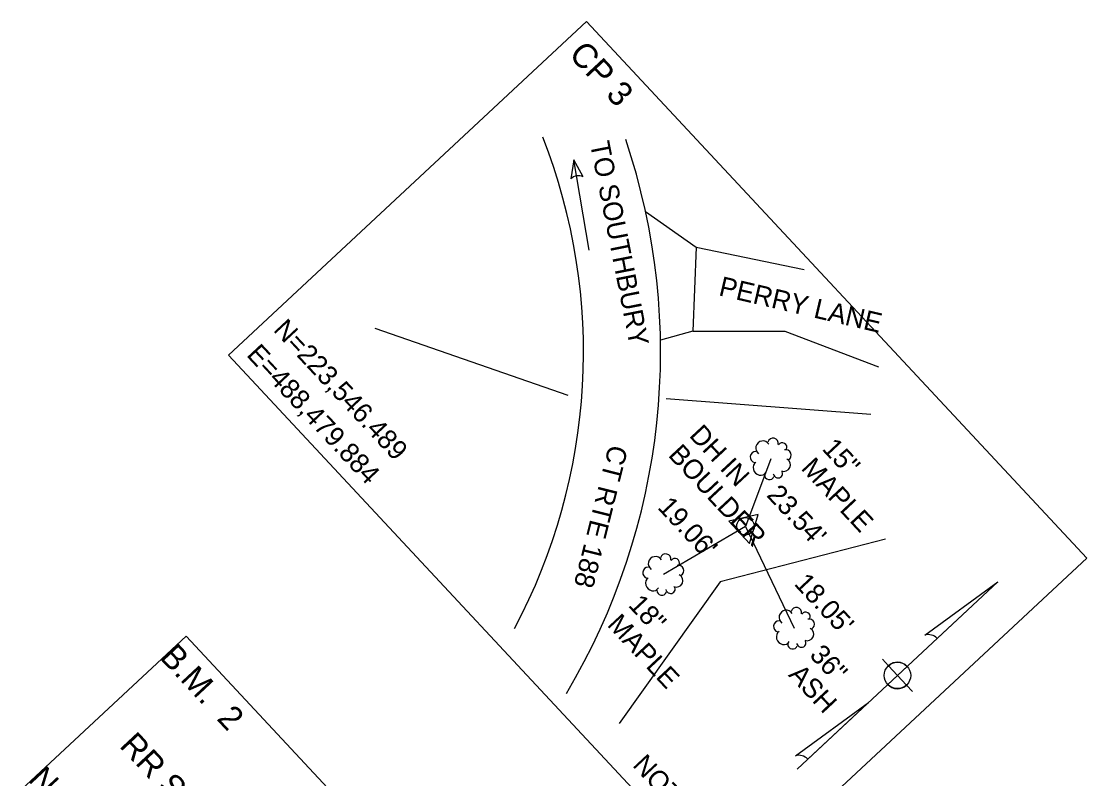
# Model space of a CAD drawing. Extents: x 487096 to 489566, y 221939 to 224454.
# Drawn here: x 488529.7 to 488704, y 223512.7 to 223636.5 of the extents above; entities that cross this region are included whole.
import ezdxf

# ---------------------------------------------------------------- set-up
doc = ezdxf.new("R2010")
doc.units = 0
doc.layers.add('SV_CTRL_BM_INFO_BOX', color=7, linetype='Continuous')
doc.layers.add('SV_CTRL_TIE_BOX', color=7, linetype='Continuous')

msp = doc.modelspace()

# ---------------------------------------------------------------- linework, layer by layer
at = {"layer": 'SV_CTRL_BM_INFO_BOX'}
msp.add_lwpolyline([(488556.68, 223535.96), (488642.46, 223443.98), (488615.51, 223418.85), (488529.73, 223510.83)], close=True, dxfattribs=at)
at = {"layer": 'SV_CTRL_TIE_BOX'}
for p, q in [((488620.13, 223613.86), (488619.64, 223610.73)), ((488622.64, 223599.07), (488620.13, 223613.86)), ((488621.62, 223611.07), (488620.13, 223613.86)), ((488640.14, 223599.58), (488657.8, 223595.93)), ((488619.21, 223575.33), (488587.59, 223586.3)), ((488668.67, 223572.19), (488635.24, 223574.77)), ((488652.36, 223564.95), (488652.36, 223564.95)), ((488650.28, 223555.88), (488645.44, 223554.76)), ((488645.44, 223554.76), (488648.83, 223551.13)), ((488648.83, 223551.13), (488650.28, 223555.88)), ((488648.18, 223553.92), (488634.78, 223546.04)), ((488648.18, 223553.92), (488648.18, 223553.92)), ((488634.78, 223546.04), (488634.78, 223546.04)), ((488656.63, 223514.24), (488689.47, 223544.86)), ((488656.17, 223537.26), (488656.17, 223537.26)), ((488679.53, 223535.6), (488679.53, 223535.6)), ((488679.53, 223535.6), (488679.53, 223535.6)), ((488670.59, 223532.19), (488671.58, 223531.13)), ((488671.58, 223531.13), (488673.05, 223529.55)), ((488673.05, 223529.55), (488674.63, 223531.03)), ((488671.47, 223528.08), (488673.05, 223529.55)), ((488673.05, 223529.55), (488673.05, 223529.55)), ((488673.05, 223529.55), (488674.52, 223527.97)), ((488674.52, 223527.97), (488675.5, 223526.92)), ((488656.37, 223516.41), (488668.3, 223525.12)), ((488658.36, 223515.85), (488668.3, 223525.12)), ((488668.3, 223525.12), (488658.36, 223515.86))]:
    msp.add_line(p, q, dxfattribs=at)
msp.add_lwpolyline([(488563.65, 223581.94), (488645.49, 223494.18), (488704, 223548.74), (488622.16, 223636.5)], close=True, dxfattribs=at)
for points in [[(488631.85, 223605.39), (488640.14, 223599.58), (488639.55, 223585.83), (488634.29, 223584.34)], [(488639.55, 223585.83), (488654.63, 223585.84), (488669.94, 223579.99)], [(488652.36, 223564.95), (488648.18, 223553.92), (488656.17, 223537.26)], [(488671.1, 223551.82), (488644.07, 223544.84), (488627.53, 223521.67)], [(488677.54, 223536.15), (488689.47, 223544.86), (488679.53, 223535.6), (488679.53, 223535.6)], [(488677.54, 223536.15), (488689.47, 223544.86), (488679.53, 223535.6), (488679.53, 223535.6)], [(488677.54, 223536.15), (488689.47, 223544.86), (488679.53, 223535.6), (488679.53, 223535.6)]]:
    msp.add_lwpolyline(points, dxfattribs=at)
for centre, radius in [((488648.18, 223553.92), 1.43), ((488673.05, 223529.55), 2.16)]:
    msp.add_circle(centre, radius, dxfattribs=at)
for centre, radius, start, end in [((488525.52, 223582.41), 96.17, 331.9856, 21.4355), ((488525.52, 223582.41), 108.78, 329.1397, 18.641), ((488620.85, 223609.62), 1.64, 62.0409, 137.2426), ((488651.04, 223566.72), 1.17, 32.3292, 232.9889), ((488652.7, 223567.47), 0.874, 348.9933, 164.459), ((488654.22, 223566.84), 0.75, 336.2911, 145.3579), ((488649.88, 223565.26), 0.922, 90.0157, 257.5501), ((488654.82, 223565.59), 0.85, 298.5308, 105.7093), ((488654.48, 223563.97), 1.06, 247.1859, 64.1082), ((488635.12, 223548.55), 0.874, 348.9933, 164.459), ((488633.46, 223547.81), 1.17, 32.3292, 232.9889), ((488636.64, 223547.93), 0.75, 336.2911, 145.3579), ((488632.3, 223546.35), 0.922, 90.0157, 257.5501), ((488636.9, 223545.05), 1.06, 247.1859, 64.1082), ((488637.24, 223546.68), 0.85, 298.5308, 105.7093), ((488656.5, 223539.78), 0.874, 348.9933, 164.459), ((488654.85, 223539.04), 1.17, 32.3292, 232.9889), ((488658.03, 223539.15), 0.75, 336.2911, 145.3579), ((488653.69, 223537.57), 0.922, 90.0157, 257.5501), ((488658.29, 223536.28), 1.06, 247.1859, 64.1082), ((488658.62, 223537.91), 0.85, 298.5308, 105.7093), ((488678.08, 223534.24), 1.99, 43, 105.6885), ((488678.08, 223534.24), 1.99, 43, 105.6885), ((488673.05, 223529.55), 2.16, 43, 132.985), ((488673.05, 223529.55), 2.18, 223, 313.0149), ((488656.91, 223514.5), 1.99, 43, 105.6885)]:
    msp.add_arc(centre, radius, start, end, dxfattribs=at)
for centre, major_axis, ratio, start_param, end_param in [((488650.57, 223563.45), (-0.699, 0.983), 0.902156, 0, 3.5401), ((488652.09, 223562.35), (-0.529, -0.603), 0.999752, 5.391582, 8.241319), ((488653.47, 223562.63), (0.551, -0.61), 0.901056, 4.216583, 7.444153), ((488632.98, 223544.54), (-0.699, 0.983), 0.902156, 0, 3.5401), ((488634.51, 223543.44), (-0.529, -0.603), 0.999752, 5.391582, 8.241319), ((488635.89, 223543.72), (0.551, -0.61), 0.901056, 4.216583, 7.444153), ((488654.37, 223535.76), (-0.699, 0.983), 0.902156, 0, 3.5401), ((488655.9, 223534.66), (-0.529, -0.603), 0.999752, 5.391582, 8.241319), ((488657.28, 223534.94), (0.551, -0.61), 0.901056, 4.216583, 7.444153)]:
    msp.add_ellipse(centre, major_axis=major_axis, ratio=ratio, start_param=start_param, end_param=end_param, dxfattribs=at)

# ---------------------------------------------------------------- texts
at = {"layer": 'SV_CTRL_BM_INFO_BOX'}
for s, p in [(' B.M.  2   ', (488551.2, 223533.51)), (' RR SPIKE IN 24" MAPLE                    ', (488544.64, 223519.01)), (' NGVD 1929', (488529.72, 223513.48))]:
    msp.add_text(s, height=3.937, rotation=313, dxfattribs=at).set_placement(p)
at = {"layer": 'SV_CTRL_TIE_BOX'}
for s, height, rotation, p in [('CP 3                           ', 4, 312.965, (488619.13, 223630.95)), ('TO SOUTHBURY', 3.2, 281.1204, (488622.73, 223616.56)), ('PERRY LANE', 3.2, 346.851, (488643.67, 223591.72)), ('N=223,546.489  ', 3.2, 313, (488570.83, 223585.96)), ('E=488,479.884  ', 3.2, 313, (488566.44, 223581.87)), ('DH IN', 3.2, 313, (488638.84, 223568.69)), ('CT RTE 188', 3.2, 255.9052, (488625.89, 223567.41)), ('BOULDER', 3.2, 313, (488635.4, 223565.48)), ('15"', 3.2, 313, (488660.57, 223566.52)), ('MAPLE', 3.2, 313, (488657.13, 223563.31)), ("23.54'", 3.2, 313, (488651.51, 223558.92)), ("19.06'", 3.2, 313, (488633.66, 223556.94)), ("18.05'", 3.2, 313, (488656, 223544.44)), ('18"', 3.2, 313, (488628.87, 223540.94)), ('MAPLE', 3.2, 313, (488625.43, 223537.74)), ('36"', 3.2, 313, (488658.52, 223532.75)), ('ASH', 3.2, 313, (488655.08, 223529.54)), ('NOT TO SCALE', 3.2, 313, (488629.58, 223514.77))]:
    msp.add_text(s, height=height, rotation=rotation, dxfattribs=at).set_placement(p)

doc.saveas('drawing.dxf')
